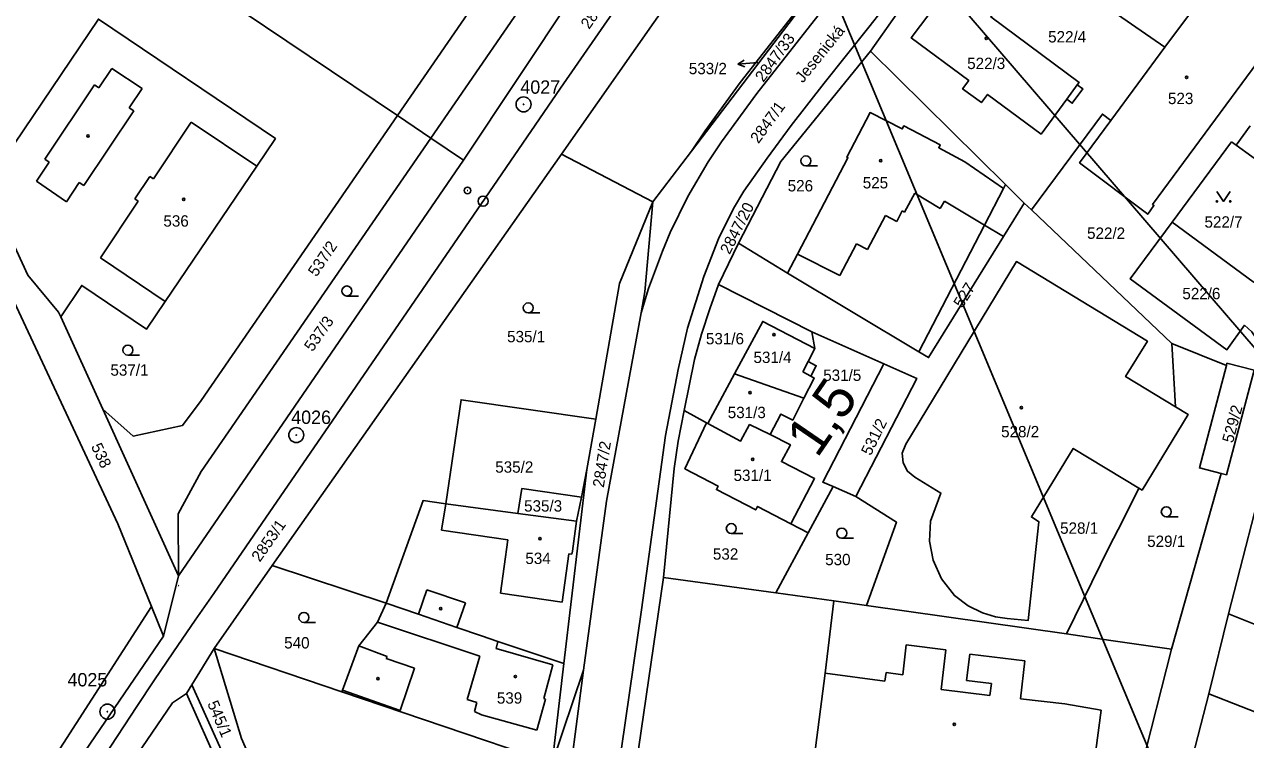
# Model space of a CAD drawing. Extents: x -558358 to -557517, y -1073785 to -1073189.
# Drawn here: x -558258 to -558075.5, y -1073555.9 to -1073448.9 of the extents above; entities that cross this region are included whole.
import ezdxf

# ---------------------------------------------------------------- set-up
doc = ezdxf.new("R2010")
doc.units = 0
for name, color, linetype in [('Hranice parcel', 7, 'Continuous'), ('Kolej', 7, 'Continuous'), ('nové prvky ZZ', 7, 'Continuous'), ('Návěst místo trati', 7, 'Continuous'), ('Parcelní čísla', 7, 'Continuous'), ('Pop  PČ popisy', 7, 'Continuous'), ('Svazek obcí údolí Desné', 7, 'Continuous'), ('Vnitřní kresba', 7, 'Continuous'), ('Vrstva 1', 7, 'Continuous'), ('Vrstva 28', 7, 'Continuous'), ('Vrstva 60', 7, 'Continuous'), ('Značky budov', 7, 'Continuous'), ('Značky kultur', 7, 'Continuous')]:
    doc.layers.add(name, color=color, linetype=linetype)

msp = doc.modelspace()

# ---------------------------------------------------------------- linework, layer by layer
at = {"layer": 'Hranice parcel'}
for p, q in [((-558197.28, -1073465.89), (-558161.06, -1073413.25)), ((-558158.31, -1073467.84), (-558131.5, -1073432.67)), ((-558131.54, -1073452.88), (-558116.63, -1073431.7)), ((-558202.26, -1073462.53), (-558233.8, -1073441.26)), ((-558087.54, -1073452.3), (-558079.09, -1073440.91)), ((-558111.36, -1073472.82), (-558131.54, -1073452.88)), ((-558087.54, -1073452.3), (-558095.61, -1073463.24)), ((-558197.28, -1073465.89), (-558202.26, -1073462.53)), ((-558076.9, -1073466.92), (-558074.8, -1073464.07)), ((-558192.36, -1073469.21), (-558197.28, -1073465.89)), ((-558158.31, -1073467.84), (-558156.26, -1073464.79)), ((-558164.08, -1073475.42), (-558158.31, -1073467.84)), ((-558086.45, -1073478.46), (-558077.57, -1073466.44)), ((-558077.57, -1073466.44), (-558076.9, -1073466.92)), ((-558076.9, -1073466.92), (-558072.2, -1073470.34)), ((-558164.08, -1073475.42), (-558177.75, -1073468.29)), ((-558108.55, -1073475.6), (-558111.36, -1073472.82)), ((-558111.65, -1073480.62), (-558108.55, -1073475.6)), ((-558108.55, -1073475.6), (-558107.49, -1073476.62)), ((-558107.49, -1073476.62), (-558086.48, -1073496.61)), ((-558154.26, -1073487.77), (-558151.25, -1073481.61)), ((-558151.25, -1073481.61), (-558143.96, -1073486.09)), ((-558143.96, -1073486.09), (-558124.31, -1073497.86)), ((-558140.32, -1073494.88), (-558154.26, -1073487.77)), ((-558164.73, -1073488.39), (-558165.84, -1073492.01)), ((-558246.29, -1073506.44), (-558252.58, -1073492.61)), ((-558140.32, -1073494.88), (-558139.88, -1073497.35)), ((-558129.53, -1073499.66), (-558140.32, -1073494.88)), ((-558085.97, -1073506.08), (-558086.48, -1073496.61)), ((-558086.48, -1073496.61), (-558078.35, -1073499.89)), ((-558078.35, -1073499.89), (-558078.27, -1073499.57)), ((-558074.22, -1073500.6), (-558078.34, -1073516.28)), ((-558078.27, -1073499.57), (-558074.22, -1073500.6)), ((-558151.86, -1073501.13), (-558155.87, -1073508.56)), ((-558141.49, -1073504.81), (-558151.86, -1073501.13)), ((-558234.96, -1073531.36), (-558246.29, -1073506.44)), ((-558172.6, -1073507.93), (-558173.92, -1073515.47)), ((-558159.39, -1073506.66), (-558156.05, -1073508.46)), ((-558155.87, -1073508.56), (-558156.05, -1073508.46)), ((-558072, -1073513.63), (-558078.01, -1073537.04)), ((-558177.37, -1073544.49), (-558173.92, -1073515.47)), ((-558173.92, -1073515.47), (-558174.76, -1073519.59)), ((-558079.12, -1073516.08), (-558086.54, -1073542.34)), ((-558078.34, -1073516.28), (-558079.12, -1073516.08)), ((-558137.14, -1073518.03), (-558140.85, -1073524.92)), ((-558133.75, -1073519.51), (-558137.14, -1073518.03)), ((-558184.24, -1073522.04), (-558195.03, -1073520.62)), ((-558234.96, -1073531.36), (-558235.03, -1073522.1)), ((-558143.44, -1073523.57), (-558140.85, -1073524.92)), ((-558140.85, -1073524.92), (-558145.69, -1073533.93)), ((-558203.93, -1073535.45), (-558220.99, -1073529.81)), ((-558162.5, -1073531.6), (-558145.69, -1073533.93)), ((-558145.69, -1073533.93), (-558137.04, -1073535.13)), ((-558137.04, -1073535.13), (-558132.14, -1073535.81)), ((-558102.24, -1073540.03), (-558132.14, -1073535.81)), ((-558078.01, -1073537.04), (-558080.96, -1073549.01)), ((-558078.01, -1073537.04), (-558050.57, -1073548.21)), ((-558229.66, -1073542.22), (-558210.55, -1073548.74)), ((-558179.14, -1073559.41), (-558177.37, -1073544.49)), ((-558179.14, -1073559.41), (-558174.43, -1073545.49)), ((-558174.43, -1073545.49), (-558176.44, -1073560.75)), ((-558218.9, -1073578.68), (-558232.98, -1073547.69)), ((-558220.27, -1073579.28), (-558233.76, -1073548.97)), ((-558210.55, -1073548.74), (-558179.99, -1073559.12)), ((-558080.96, -1073549.01), (-558086.83, -1073571.83)), ((-558080.96, -1073549.01), (-558055.56, -1073559.09))]:
    msp.add_line(p, q, dxfattribs=at)
for points in [[(-558086.19, -1073392.25), (-558100.56, -1073410.01), (-558117.51, -1073431.08), (-558131.78, -1073449.27), (-558138.48, -1073457.68), (-558143.38, -1073464.02), (-558146.99, -1073468.89), (-558150.46, -1073473.83), (-558152.02, -1073476.41), (-558154.26, -1073480.97), (-558156.46, -1073486.6), (-558158.91, -1073494.31), (-558160.3, -1073500.48), (-558162.16, -1073510.4), (-558165.76, -1073536.46), (-558169.94, -1073565.43), (-558173.74, -1073591.61), (-558177.66, -1073620.33), (-558178.51, -1073631.87), (-558179.02, -1073643), (-558179.24, -1073655.12), (-558179.45, -1073666.94), (-558179.49, -1073675.4)], [(-558202.26, -1073462.53), (-558188.73, -1073442.87), (-558187.31, -1073436.01), (-558191.04, -1073430.36), (-558216.02, -1073413.17)], [(-558156.26, -1073464.79), (-558151.01, -1073457.58), (-558133.63, -1073435.37), (-558133.35, -1073433.74), (-558133.31, -1073429.98), (-558133.56, -1073429.34)], [(-558129.07, -1073430.81), (-558128.89, -1073431.83), (-558128.89, -1073432.84), (-558129.1, -1073433.85), (-558129.56, -1073434.77), (-558130.67, -1073436.36), (-558148.52, -1073459.19), (-558153.8, -1073466.46), (-558155.8, -1073469.46), (-558158.84, -1073474.63), (-558161.5, -1073480.01), (-558162.64, -1073482.78), (-558164.73, -1073488.39)], [(-558112.83, -1073434.1), (-558108.9, -1073437.49), (-558087.54, -1073452.3)], [(-558115.24, -1073437.31), (-558125.46, -1073450.9), (-558116.85, -1073457.27), (-558117.77, -1073458.51), (-558114.97, -1073460.58), (-558114.05, -1073459.35), (-558106.05, -1073465.28), (-558102.2, -1073460.05)], [(-558100.63, -1073457.93), (-558100.36, -1073457.56), (-558113.55, -1073447.75), (-558109, -1073442.11), (-558111.2, -1073440.45), (-558110.8, -1073439.94)], [(-558252.58, -1073492.61), (-558249.44, -1073487.92), (-558239.75, -1073494.46), (-558236.97, -1073490.34), (-558223.28, -1073470.09), (-558220.49, -1073465.96), (-558246.94, -1073448.09), (-558263.73, -1073472.95)], [(-558069.01, -1073448.19), (-558089.39, -1073475.8), (-558089.17, -1073475.95), (-558090.09, -1073477.27), (-558100.29, -1073469.58), (-558095.61, -1073463.24)], [(-558151.25, -1073481.61), (-558144.94, -1073469.39), (-558131.54, -1073452.88)], [(-558102.2, -1073460.05), (-558101.38, -1073460.67), (-558099.8, -1073458.54), (-558100.63, -1073457.93)], [(-558111.36, -1073472.82), (-558111.67, -1073473.41), (-558117.43, -1073469.44), (-558121.34, -1073467.34), (-558121.11, -1073466.9), (-558126.57, -1073464.07), (-558126.8, -1073464.51), (-558131.6, -1073462.08), (-558135.08, -1073468.74), (-558134.91, -1073468.83), (-558142.45, -1073483.25), (-558143.96, -1073486.09)], [(-558095.61, -1073463.24), (-558096.89, -1073462.29), (-558107.49, -1073476.62)], [(-558246.29, -1073506.44), (-558241.75, -1073510.46), (-558234.37, -1073508.88), (-558231.59, -1073505.15), (-558202.26, -1073462.53)], [(-558235.03, -1073522.1), (-558231.61, -1073515.78), (-558197.28, -1073465.89)], [(-558263.73, -1073472.95), (-558257.48, -1073486.4), (-558252.9, -1073491.92), (-558252.58, -1073492.61)], [(-558164.08, -1073475.42), (-558169.06, -1073487.65), (-558172.6, -1073507.93)], [(-558165.84, -1073492.01), (-558165.27, -1073488.87), (-558164.08, -1073475.42)], [(-558073.57, -1073498.15), (-558073.51, -1073497.13), (-558073.7, -1073496.11), (-558074.52, -1073494.85), (-558075.64, -1073493.89), (-558078.28, -1073497.56), (-558092.71, -1073486.96), (-558086.45, -1073478.46)], [(-558070.38, -1073485.35), (-558070.76, -1073486.43), (-558071.41, -1073487.24), (-558072.33, -1073487.8), (-558073.38, -1073487.88), (-558074.36, -1073487.41), (-558086.45, -1073478.46)], [(-558124.31, -1073497.86), (-558114.5, -1073478.9), (-558111.65, -1073480.62)], [(-558124.31, -1073497.86), (-558122.86, -1073498.73), (-558111.65, -1073480.62)], [(-558091.42, -1073518.26), (-558101.25, -1073512.3), (-558107.5, -1073522.55), (-558106.36, -1073523.27), (-558107.97, -1073538.05), (-558111.12, -1073537.73), (-558112.87, -1073537.48), (-558114.81, -1073536.91), (-558116.94, -1073535.87), (-558118.99, -1073534.32), (-558120.94, -1073531.84), (-558122.18, -1073529.05), (-558122.71, -1073526.18), (-558122.56, -1073523.2), (-558121.01, -1073518.98), (-558124.91, -1073516.6), (-558126.01, -1073515.72), (-558126.67, -1073514.49), (-558126.79, -1073513.04), (-558126.28, -1073511.65), (-558109.74, -1073484.35), (-558090.14, -1073496.27), (-558093.41, -1073501.56), (-558085.97, -1073506.08)], [(-558159.39, -1073506.66), (-558157.84, -1073498.99), (-558156.78, -1073495.22), (-558155.58, -1073491.43), (-558154.26, -1073487.77)], [(-558259.89, -1073489.61), (-558244.04, -1073523.6), (-558239.03, -1073535.96)], [(-558165.84, -1073492.01), (-558171, -1073520.22), (-558174.43, -1073545.49)], [(-558139.88, -1073497.35), (-558147.64, -1073493.32), (-558151.86, -1073501.13)], [(-558141.49, -1073504.81), (-558139.95, -1073501.78), (-558140.44, -1073501.51), (-558139.64, -1073499.94), (-558140.88, -1073499.3), (-558139.88, -1073497.35)], [(-558129.53, -1073499.66), (-558138.67, -1073517.37), (-558137.14, -1073518.03)], [(-558133.75, -1073519.51), (-558124.62, -1073501.83), (-558129.53, -1073499.66)], [(-558078.35, -1073499.89), (-558082.38, -1073515.23), (-558079.12, -1073516.08)], [(-558195.03, -1073520.62), (-558192.73, -1073505.02), (-558172.6, -1073507.93)], [(-558146.56, -1073510.24), (-558144.94, -1073507.17), (-558143.16, -1073508.08), (-558141.49, -1073504.81)], [(-558091.42, -1073518.26), (-558090.96, -1073518.54), (-558084.08, -1073507.23), (-558085.97, -1073506.08)], [(-558162.5, -1073531.6), (-558160.9, -1073515.3), (-558160.3, -1073511.2), (-558159.39, -1073506.66)], [(-558156.05, -1073508.46), (-558159.29, -1073515.35), (-558154.32, -1073517.94), (-558154.58, -1073518.47), (-558148.69, -1073521.52), (-558148.41, -1073520.99), (-558143.44, -1073523.57)], [(-558146.56, -1073510.24), (-558149.62, -1073508.74), (-558150.95, -1073511.21), (-558155.87, -1073508.56)], [(-558143.44, -1073523.57), (-558139.9, -1073516.83), (-558144.85, -1073514.28), (-558143.52, -1073511.79), (-558146.56, -1073510.24)], [(-558184.24, -1073522.04), (-558183.68, -1073518.31), (-558174.76, -1073519.59)], [(-558102.24, -1073540.03), (-558095.9, -1073527.13), (-558093.83, -1073523.1), (-558091.42, -1073518.26)], [(-558195.03, -1073520.62), (-558198.39, -1073520.09), (-558203.93, -1073535.45)], [(-558174.76, -1073519.59), (-558175.5, -1073523.19), (-558184.24, -1073522.04)], [(-558132.14, -1073535.81), (-558127.68, -1073523.33), (-558133.75, -1073519.51)], [(-558169.56, -1073582.12), (-558166.59, -1073559.69), (-558162.5, -1073531.6)], [(-558137.04, -1073535.13), (-558138.34, -1073545.94), (-558140.1, -1073559.78), (-558127.81, -1073561.38), (-558128.13, -1073563.82), (-558128.85, -1073568.77)], [(-558203.93, -1073535.45), (-558205.25, -1073538.29), (-558208.03, -1073541.86), (-558210.44, -1073548.45), (-558210.55, -1073548.74)], [(-558203.93, -1073535.45), (-558199.11, -1073537.11), (-558193.35, -1073539.1), (-558189.69, -1073540.36), (-558187.24, -1073541.19), (-558177.37, -1073544.49)], [(-558086.54, -1073542.34), (-558095.62, -1073541.02), (-558102.24, -1073540.03)], [(-558219.67, -1073569.09), (-558225.55, -1073555.71), (-558229.66, -1073542.22)], [(-558099.6, -1073591.18), (-558091.09, -1073560.2), (-558086.54, -1073542.34)]]:
    msp.add_lwpolyline(points, dxfattribs=at)
at = {"layer": 'Kolej'}
for points in [[(-558222.5, -1073523.52), (-558211.35, -1073507.26), (-558189.16, -1073474.89), (-558177.86, -1073458.42), (-558166.63, -1073442.09)], [(-558246.06, -1073558.3), (-558241.22, -1073550.9), (-558238.65, -1073547.06), (-558235.71, -1073542.74), (-558232.47, -1073538.02), (-558229.71, -1073534.01), (-558222.5, -1073523.52)]]:
    msp.add_lwpolyline(points, dxfattribs=at)
at = {"layer": 'nové prvky ZZ'}
for p, q in [((-558234.94, -1073532.87), (-558235.04, -1073532.8)), ((-558233.36, -1073548.08), (-558233.26, -1073548.14))]:
    msp.add_line(p, q, dxfattribs=at)
at = {"layer": 'Návěst místo trati'}
msp.add_line((-558191.83, -1073473.72), (-558191.73, -1073473.72), dxfattribs=at)
for centre, radius in [((-558191.78, -1073473.72), 0.5), ((-558189.45, -1073475.32), 0.75)]:
    msp.add_circle(centre, radius, dxfattribs=at)
at = {"layer": 'Pop  PČ popisy'}
for p, q in [((-558151.36, -1073454.83), (-558150.41, -1073454.25)), ((-558148.37, -1073454.57), (-558151.36, -1073454.83)), ((-558151.36, -1073454.83), (-558150.32, -1073455.24))]:
    msp.add_line(p, q, dxfattribs=at)
at = {"layer": 'Svazek obcí údolí Desné'}
for p, q in [((-558138.47, -1073412.32), (-558177.75, -1073468.29)), ((-558157.08, -1073415.91), (-558192.36, -1073469.21)), ((-558192.36, -1073469.21), (-558234.96, -1073531.36)), ((-558177.75, -1073468.29), (-558220.99, -1073529.81)), ((-558220.99, -1073529.81), (-558229.66, -1073542.22)), ((-558234.96, -1073531.36), (-558237.23, -1073540.41)), ((-558239.03, -1073535.96), (-558237.23, -1073540.41)), ((-558229.66, -1073542.22), (-558232.98, -1073547.69)), ((-558232.98, -1073547.69), (-558233.76, -1073548.97))]:
    msp.add_line(p, q, dxfattribs=at)
for points in [[(-558286.79, -1073633.11), (-558279.73, -1073611.9), (-558267.63, -1073584.34), (-558254.51, -1073560.06), (-558239.03, -1073535.96)], [(-558237.23, -1073540.41), (-558250.35, -1073559.71), (-558264.4, -1073584.99), (-558277.08, -1073613.49), (-558283.33, -1073632.3), (-558290.3, -1073658.29), (-558296.01, -1073700.28), (-558297.13, -1073716.84), (-558297.21, -1073758.56)], [(-558233.76, -1073548.97), (-558235.85, -1073550.36), (-558241.19, -1073558.21), (-558248.9, -1073570.88), (-558258.93, -1073588.36)]]:
    msp.add_lwpolyline(points, dxfattribs=at)
at = {"layer": 'Vnitřní kresba'}
for p, q in [((-558246.86, -1073458.35), (-558244.94, -1073455.47)), ((-558244.94, -1073455.47), (-558240.43, -1073458.48)), ((-558254.96, -1073469.03), (-558247.53, -1073457.9)), ((-558247.53, -1073457.9), (-558246.86, -1073458.35)), ((-558242.35, -1073461.35), (-558240.43, -1073458.48)), ((-558100.63, -1073457.93), (-558102.2, -1073460.05)), ((-558249.13, -1073472.99), (-558241.66, -1073461.81)), ((-558242.35, -1073461.35), (-558241.66, -1073461.81)), ((-558238.73, -1073471.97), (-558233.06, -1073463.5)), ((-558233.06, -1073463.5), (-558223.28, -1073470.09)), ((-558256.21, -1073472.34), (-558254.3, -1073469.47)), ((-558254.96, -1073469.03), (-558254.3, -1073469.47)), ((-558256.21, -1073472.34), (-558251.73, -1073475.41)), ((-558251.73, -1073475.41), (-558249.81, -1073472.53)), ((-558249.81, -1073472.53), (-558249.13, -1073472.99)), ((-558241.52, -1073474.97), (-558239.27, -1073471.61)), ((-558239.27, -1073471.61), (-558238.73, -1073471.97)), ((-558241.52, -1073474.97), (-558240.98, -1073475.33)), ((-558126.45, -1073476.96), (-558124.93, -1073474.1)), ((-558124.93, -1073474.1), (-558121.12, -1073476.4)), ((-558114.5, -1073478.9), (-558111.67, -1073473.41)), ((-558246.65, -1073483.79), (-558240.98, -1073475.33)), ((-558127.63, -1073478.35), (-558126.79, -1073476.79)), ((-558126.79, -1073476.79), (-558126.45, -1073476.96)), ((-558121.12, -1073476.4), (-558120.46, -1073475.31)), ((-558120.46, -1073475.31), (-558114.5, -1073478.9)), ((-558132, -1073482.54), (-558129.3, -1073477.44)), ((-558129.3, -1073477.44), (-558127.63, -1073478.35)), ((-558136.15, -1073486.45), (-558133.63, -1073481.7)), ((-558133.63, -1073481.7), (-558132, -1073482.54)), ((-558246.65, -1073483.79), (-558236.97, -1073490.34)), ((-558142.45, -1073483.25), (-558136.15, -1073486.45)), ((-558141.68, -1073500.85), (-558140.88, -1073499.3)), ((-558141.68, -1073500.85), (-558140.44, -1073501.51)), ((-558195.64, -1073524.53), (-558195.03, -1073520.62)), ((-558176.08, -1073527.66), (-558175.5, -1073523.19)), ((-558195.64, -1073524.53), (-558185.73, -1073525.99)), ((-558186.85, -1073533.98), (-558185.73, -1073525.99)), ((-558176.18, -1073528.11), (-558176.08, -1073527.66)), ((-558177.65, -1073535.29), (-558176.63, -1073528.09)), ((-558176.63, -1073528.09), (-558176.18, -1073528.11)), ((-558199.11, -1073537.11), (-558197.85, -1073533.46)), ((-558197.85, -1073533.46), (-558192.08, -1073535.4)), ((-558186.85, -1073533.98), (-558177.65, -1073535.29)), ((-558193.35, -1073539.1), (-558192.08, -1073535.4)), ((-558205.25, -1073538.29), (-558189.93, -1073543.4)), ((-558208.03, -1073541.86), (-558203.81, -1073543.44)), ((-558187.49, -1073542.24), (-558187.24, -1073541.19)), ((-558187.49, -1073542.24), (-558179, -1073544.67)), ((-558126.72, -1073546.2), (-558126.22, -1073541.7)), ((-558126.22, -1073541.7), (-558120.27, -1073542.43)), ((-558121, -1073548.38), (-558120.27, -1073542.43)), ((-558203.92, -1073543.72), (-558203.81, -1073543.44)), ((-558203.92, -1073543.72), (-558199.71, -1073545.18)), ((-558191.85, -1073549.89), (-558189.93, -1073543.4)), ((-558117.17, -1073547.04), (-558116.72, -1073543.11)), ((-558116.72, -1073543.11), (-558108.48, -1073544.08)), ((-558109.12, -1073549.75), (-558108.48, -1073544.08)), ((-558201.86, -1073551.5), (-558199.71, -1073545.18)), ((-558180.35, -1073549.71), (-558179, -1073544.67)), ((-558138.34, -1073545.94), (-558129.39, -1073547.14)), ((-558129.39, -1073547.14), (-558129.22, -1073545.83)), ((-558129.22, -1073545.83), (-558126.72, -1073546.2)), ((-558117.17, -1073547.04), (-558113.48, -1073547.47)), ((-558113.69, -1073549.26), (-558113.48, -1073547.47)), ((-558210.44, -1073548.45), (-558201.86, -1073551.5)), ((-558191.85, -1073549.89), (-558190.36, -1073550.31)), ((-558181.43, -1073554.48), (-558180.14, -1073549.84)), ((-558180.35, -1073549.71), (-558180.14, -1073549.84)), ((-558121, -1073548.38), (-558113.69, -1073549.26)), ((-558109.12, -1073549.75), (-558102.5, -1073550.54)), ((-558190.71, -1073551.65), (-558190.36, -1073550.31)), ((-558190.71, -1073551.65), (-558189.68, -1073552.16)), ((-558102.5, -1073550.54), (-558097.04, -1073551.46)), ((-558097.85, -1073557.5), (-558097.04, -1073551.46)), ((-558189.68, -1073552.16), (-558181.43, -1073554.48))]:
    msp.add_line(p, q, dxfattribs=at)
at = {"layer": 'Vrstva 28'}
for p, q in [((-558150.5, -1073408.33), (-557941.76, -1073651.48)), ((-558150.16, -1073413.05), (-558044.9, -1073665.43))]:
    msp.add_line(p, q, dxfattribs=at)
at = {"layer": 'Vrstva 60'}
for p, q in [((-558183.4, -1073460.84), (-558183.4, -1073460.84)), ((-558183.4, -1073460.84), (-558183.4, -1073460.84)), ((-558217.37, -1073510.31), (-558217.37, -1073510.31)), ((-558217.37, -1073510.31), (-558217.37, -1073510.31)), ((-558245.6, -1073551.69), (-558245.6, -1073551.69)), ((-558245.6, -1073551.69), (-558245.6, -1073551.69))]:
    msp.add_line(p, q, dxfattribs=at)
for centre, radius in [((-558183.4, -1073460.84), 1.12), ((-558183.4, -1073460.84), 1.12), ((-558183.4, -1073460.84), 0.045), ((-558183.4, -1073460.84), 0.045), ((-558217.37, -1073510.31), 1.12), ((-558217.37, -1073510.31), 1.12), ((-558217.37, -1073510.31), 0.045), ((-558217.37, -1073510.31), 0.045), ((-558245.6, -1073551.69), 1.12), ((-558245.6, -1073551.69), 1.12), ((-558245.6, -1073551.69), 0.045), ((-558245.6, -1073551.69), 0.045)]:
    msp.add_circle(centre, radius, dxfattribs=at)
at = {"layer": 'Značky budov'}
for centre in [(-558114.25, -1073450.97), (-558084.29, -1073456.8), (-558248.48, -1073465.56), (-558130.01, -1073469.27), (-558234.2, -1073475.05), (-558145.97, -1073495.27), (-558149.53, -1073503.95), (-558108.99, -1073506.2), (-558149.15, -1073513.95), (-558180.95, -1073525.8), (-558195.77, -1073536.28), (-558184.62, -1073546.43), (-558205.18, -1073546.74), (-558119.02, -1073553.6)]:
    msp.add_circle(centre, 0.175, dxfattribs=at)
at = {"layer": 'Značky kultur'}
for p, q in [((-558141.2, -1073470.05), (-558139.45, -1073470.05)), ((-558209.8, -1073489.51), (-558208.05, -1073489.51)), ((-558182.7, -1073492.04), (-558180.95, -1073492.04)), ((-558242.54, -1073498.35), (-558240.79, -1073498.35)), ((-558087.33, -1073522.53), (-558085.58, -1073522.53)), ((-558152.35, -1073525.05), (-558150.6, -1073525.05)), ((-558135.84, -1073525.74), (-558134.09, -1073525.74)), ((-558216.23, -1073538.34), (-558214.48, -1073538.34))]:
    msp.add_line(p, q, dxfattribs=at)
msp.add_lwpolyline([(-558079.77, -1073473.86), (-558078.77, -1073475.36), (-558077.77, -1073473.86)], dxfattribs=at)
for centre, radius in [((-558141.2, -1073469.3), 0.75), ((-558079.77, -1073475.36), 0.1), ((-558077.77, -1073475.36), 0.1), ((-558209.8, -1073488.76), 0.75), ((-558182.7, -1073491.29), 0.75), ((-558242.54, -1073497.6), 0.75), ((-558087.33, -1073521.78), 0.75), ((-558152.35, -1073524.3), 0.75), ((-558135.84, -1073524.99), 0.75), ((-558216.23, -1073537.59), 0.75)]:
    msp.add_circle(centre, radius, dxfattribs=at)

# ---------------------------------------------------------------- texts
at = {"layer": 'Návěst místo trati'}
msp.add_text('1,5', height=6, rotation=55.5626, dxfattribs=at).set_placement((-558139.51, -1073513.88))
at = {"layer": 'Parcelní čísla'}
for s, rotation, p in [('2847/33', 54, (-558147.56, -1073457.63)), ('2847/1', 54, (-558148.29, -1073466.81)), ('2847/20', 63, (-558152.61, -1073483.4)), ('537/2', 56, (-558214.34, -1073486.74)), ('527', 58, (-558117.82, -1073491.43)), ('537/3', 55, (-558214.94, -1073497.94)), ('529/2', 75, (-558077.38, -1073511.59)), ('531/2', 64, (-558131.51, -1073513.5)), ('538', 295, (-558248.08, -1073512)), ('2847/2', 81, (-558171.41, -1073518.24)), ('545/1', 293, (-558230.7, -1073550.47))]:
    msp.add_text(s, height=1.7, rotation=rotation, dxfattribs=at).set_placement(p)
for s, p in [('522/4', (-558104.99, -1073451.58)), ('533/2', (-558158.7, -1073456.33)), ('522/3', (-558117.09, -1073455.56)), ('523', (-558087.08, -1073460.8)), ('526', (-558143.92, -1073473.86)), ('525', (-558132.7, -1073473.41)), ('536', (-558237.23, -1073479.13)), ('522/7', (-558081.62, -1073479.28)), ('522/2', (-558099.17, -1073480.96)), ('522/6', (-558084.93, -1073489.99)), ('535/1', (-558185.86, -1073496.43)), ('531/6', (-558156.14, -1073496.74)), ('531/4', (-558149.03, -1073499.53)), ('537/1', (-558245.15, -1073501.43)), ('531/5', (-558138.61, -1073502.21)), ('531/3', (-558152.88, -1073507.78)), ('528/2', (-558112.02, -1073510.65)), ('535/2', (-558187.63, -1073515.94)), ('531/1', (-558152.01, -1073517.18)), ('535/3', (-558183.32, -1073521.76)), ('528/1', (-558103.2, -1073525.08)), ('529/1', (-558090.19, -1073527.05)), ('534', (-558183.13, -1073529.6)), ('532', (-558155.1, -1073528.95)), ('530', (-558138.32, -1073529.78)), ('540', (-558219.18, -1073542.24)), ('539', (-558187.39, -1073550.49))]:
    msp.add_text(s, height=1.7, dxfattribs=at).set_placement(p)
at = {"layer": 'Pop  PČ popisy'}
msp.add_text('Jesenická', height=1.7, rotation=51, dxfattribs=at).set_placement((-558141.65, -1073457.73))
at = {"layer": 'Vrstva 1'}
for p in [(-558173.6, -1073449.7), (-558222.82, -1073529.41)]:
    msp.add_text('2853/1', height=1.7, rotation=55, dxfattribs=at).set_placement(p)
at = {"layer": 'Vrstva 60'}
for s, p in [('4027', (-558183.88, -1073459.25)), ('4026', (-558218.13, -1073508.65)), ('4025', (-558251.57, -1073547.91))]:
    msp.add_text(s, height=2, dxfattribs=at).set_placement(p)

doc.saveas('drawing.dxf')
